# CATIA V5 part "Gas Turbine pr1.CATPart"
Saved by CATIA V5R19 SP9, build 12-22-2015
Part number: PART1
Bounding box of the stored display mesh (mm): x -218.31 to 175.724, y -49.491 to 39.777, z -50 to 67.852
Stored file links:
  C:\Users\hdellam\Desktop\Main Folder\Practice\Turbine\PROTOTYPE.CATPart
  C:\ds\catiaV5R19\sp0a\win_b64\startup\materials\Catalog.CATMaterial
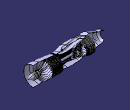
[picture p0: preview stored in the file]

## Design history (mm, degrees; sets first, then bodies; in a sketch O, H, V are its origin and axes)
AxisSystem1: origin (0, 0, 0), X (1, 0, 0), Y (0, 1, 0), Z (0, 0, 1)
Set1
  Plane1: type Offset, RefPlane zx-plane, Offset 29
  Plane2: type Offset, RefPlane Plane1, Offset 10
  Plane3: type Offset, RefPlane yz-plane, Offset -114
  Point1: (-114, 0, 0), in AxisSystem1
  Plane4: type OffsetPt, RefPlane zx-plane, RefPoint Point1
  Plane5: type Offset, RefPlane Plane4, Offset 9
  Plane6: type OffsetPt, RefPlane xy-plane, RefPoint Point1
  Plane7: type Offset, RefPlane Plane6, Offset 37
  Plane8: type Offset, RefPlane Plane5, Offset 27
  Plane9: type Offset, RefPlane zx-plane, Offset 8
  Plane10: type Offset, RefPlane Plane9, Offset 30
  Plane11: type Offset, RefPlane xy-plane, Offset 42
  Plane12: type Offset, RefPlane zx-plane, Offset 10
  Plane13: type Offset, RefPlane Plane4, Offset 19
Body1 (main body)
  Sketch1 on zx-plane, origin (0, 0, 0), H (-1, 0, 0), V (0, 0, 1)
    line L1 (-150, 50) -> (-120, 50)
    line L2 (-120, 50) -> (-30, 40)
    line L3 (-30, 40) -> (-10, 40)
    line L4 (-10, 40) -> (30, 50)
    point P5 (30, 50)
    line L5 (30, 50) -> (90, 50)
    line L6 (90, 50) -> (110, 40)
    point P7 (110, 40)
    line L7 (110, 40) -> (140, 50)
    point P8 (140, 50)
    line L8 (140, 50) -> (190, 30)
    line L9 (190, 30) -> (210, 30)
    line L10 (210, 30) -> (220, 20)
    line L11 (220, 20) -> (220, 0)
    line L12 (-150, 50) -> (-150, 0)
    horizontal: L1 H, L3 H, L5 H, L9 H
    coincidence: P5 L1, P7 L3, P8 L1
    vertical: L11 V, L12 V
  Shaft1: profile Sketch1, axis Sketch1.H, angle -180
  Shell1: IntOffset 1, Face face of Shaft1, ExtOffset 0
  Thickness1: Thickness -1, Face face of Shaft1 from Sketch1.L12
  Sketch2 on zx-plane, origin (0, 0, 0), H (-1, 0, 0), V (0, 0, 1)
    line L1 (218.3102, 24.4495) -> (218.3102, -38.2901)
    line L2 (218.3102, -38.2901) -> (240.7921, -25.6477)
    line L3 (240.7921, -25.6477) -> (239.1356, 27.4033)
    line L4 (239.1356, 27.4033) -> (218.3102, 24.4495)
    vertical: L1 V
  Pocket1: profile Sketch2, direction (0, -1, 0), length 100
  Sketch3 on zx-plane, origin (0, 0, 0), H (-1, 0, 0), V (0, 0, 1)
    line L1 (-30, 30) -> (-80, 30)
    line L2 (-80, 30) -> (-130, 10)
    line L3 (-130, 10) -> (-130, 0)
    line L4 (-30, 30) -> (-30, 0)
    horizontal: L1 H
    vertical: L3 V, L4 V
  Shaft2: profile Sketch3, axis Sketch3.H, angle 360
  Sketch4 on zx-plane, origin (0, 0, 0), H (-1, 0, 0), V (0, 0, 1)
    line L1 (-127.8768, 8.0204) -> (-137.0359, 8.0204)
    line L2 (-137.0359, 8.0204) -> (-137.0359, 0)
    line L3 (-127.8768, 0) -> (-127.8768, 8.0204)
    axis line L4 (-153.3785, 0) -> (-103.6323, 0)
    point P3 (-153.3785, 0)
    point P5 (-137.0359, 0)
    point P6 (-127.8768, 0)
    horizontal: L1 H, L4 H
    vertical: L2 V, L3 V
    coincidence: P3 H, L4 P5, L4 P6
  Shaft3: profile Sketch4, axis Sketch4.L4, angle 360
  Sketch5 on zx-plane, origin (0, 0, 0), H (-1, 0, 0), V (0, 0, 1)
    point P1 (-136.138, 0)
    line L1 (-136.138, 0) -> (-136.138, 9.2757)
    line L2 (-136.138, 9.2757) -> (-139.191, 9.2757)
    line L3 (-139.191, 9.2757) -> (-139.191, 0)
    point P4 (-139.191, 0)
    coincidence: P1 H, P4 H
    vertical: L1 V, L3 V
    horizontal: L2 H
  Shaft4: profile Sketch5, axis Sketch5.H, angle 360
  Sketch6 on zx-plane, origin (0, 0, 0), H (-1, 0, 0), V (0, 0, 1)
    line L1 (-138.293, 7.4825) -> (-138.293, 15.3729)
    line L2 (-138.293, 15.3729) -> (-151.5826, 15.3729)
    line L3 (-151.5826, 15.3729) -> (-174.6721, 1.8721)
    arc A1 centre (-173.5995, 0.0376) radius 2.1251 from (-174.6721, 1.8721) to (-175.7242, 0) ccw
    point P6 (-175.7242, 0)
    vertical: L1 V
    horizontal: L2 H
    coincidence: P6 H
    tangency: A1 L3
  Shaft5: profile Sketch6, axis Sketch6.H, angle 360
  Fillet1: radius 5, on edge [face of Shaft2 from Sketch3.L2 | face of Shaft2 from Sketch3.L1]
  Loft1: solid, Sections (Sketch12; Sketch11)
  CircPattern1: of Loft1, instances 72, angular step 5, axis from edge [XY plane of AxisSystem1 | ZX plane of AxisSystem1]
  RectPattern1: of Loft1, direction 1 instances 4, spacing 12, along edge [XY plane of AxisSystem1 | ZX plane of AxisSystem1]
  CircPattern2: of RectPattern1, instances 72, angular step 5, axis from edge [XY plane of AxisSystem1 | ZX plane of AxisSystem1]
  Sketch7 on zx-plane, origin (0, 0, 0), H (-1, 0, 0), V (0, 0, 1)
    line L1 (-30.3272, 1.5715) -> (166.7698, 1.5715)
    line L2 (166.7698, 1.5715) -> (166.7698, 0)
    point P3 (166.7698, 0)
    horizontal: L1 H
    coincidence: P3 H
    vertical: L2 V
  Shaft6: profile Sketch7, axis edge [XY plane of AxisSystem1 | ZX plane of AxisSystem1], angle 360
  Sketch8 on zx-plane, origin (0, 0, 0), H (-1, 0, 0), V (0, 0, 1)
    point P1 (166.6043, 0)
    line L1 (166.6043, 0) -> (166.6043, 10.2399)
    line L2 (166.6043, 10.2399) -> (183.4256, 0.8538)
    arc A1 centre (182.8409, -0.1941) radius 1.2 from (183.4256, 0.8538) to (184.0251, 0) cw
    point P5 (184.0251, 0)
    radius A1 = 1.2
    coincidence: P1 H, P5 H
    vertical: L1 V
    tangency: A1 L2
  Shaft7: profile Sketch8, axis edge [XY plane of AxisSystem1 | ZX plane of AxisSystem1], angle 360
  Sketch9 on zx-plane, origin (0, 0, 0), H (-1, 0, 0), V (0, 0, 1)
    point P1 (111.9435, 0)
    line L1 (111.9435, 0) -> (111.9435, 21.9862)
    line L2 (111.9435, 21.9862) -> (113.0474, 21.9862)
    line L3 (113.0474, 21.9862) -> (113.0474, 17.7975)
    line L4 (113.0474, 17.7975) -> (113.0474, 9.7257)
    line L5 (113.0474, 9.7257) -> (146.4496, 9.7257)
    line L6 (146.4496, 9.7257) -> (146.4496, 0)
    point P7 (146.4496, 0)
    coincidence: P1 H, P7 H
    vertical: L1 V, L3 V, L4 V, L6 V
    horizontal: L2 H, L5 H
  Shaft8: profile Sketch9, axis axis of face of Shaft6 from Sketch7.L1, angle 360
  Fillet2: radius 10, on edge [face of Shaft5 from Sketch6.L3 | face of Shaft5 from Sketch6.L2]
  Sketch10 on Plane5, origin (0, 9, 0), H (-1, 0, 0), V (0, 0, 1)
    line L1 (119.3854, -1.7606) -> (113.692, 2.1189)
    line L2 (113.692, 2.1189) -> (113.465, 1.7859)
    line L3 (113.465, 1.7859) -> (119.1584, -2.0937)
    line L4 (119.1584, -2.0937) -> (119.3854, -1.7606)
    perpendicularity: L2 L1
    parallelism: L3 L1, L4 L2
  Sketch11 on Plane2, origin (0, 39, 0), H (-1, 0, 0), V (0, 0, 1)
    arc A1 centre (-233.0148, -215.2939) radius 293.2905 from (-31.2101, -2.4697) to (-39.0996, 4.7429) ccw
    arc A2 centre (-4446.4823, -4752.8181) radius 6485.1431 from (-39.259, 4.6458) to (-31.4249, -2.6236) cw
    line L1 (-31.4249, -2.6236) -> (-31.2101, -2.4697)
    line L2 (-39.259, 4.6458) -> (-39.0996, 4.7429)
  Sketch12 on Plane1, origin (0, 29, 0), H (-1, 0, 0), V (0, 0, 1)
    line L1 (-30.9997, -2.4617) -> (-40.1615, 4.4428)
    line L2 (-40.1615, 4.4428) -> (-40.5706, 3.9)
    line L3 (-40.5706, 3.9) -> (-31.4088, -3.0045)
    line L4 (-31.4088, -3.0045) -> (-30.9997, -2.4617)
    perpendicularity: L2 L1
    parallelism: L3 L1, L4 L2
  Sketch13 on Plane8, origin (0, 36, 0), H (-1, 0, 0), V (0, 0, 1)
    line L1 (119.2356, -1.7219) -> (117.5085, 4.4108)
    line L2 (117.5085, 4.4108) -> (117.2852, 4.3479)
    line L3 (117.2852, 4.3479) -> (119.0124, -1.7848)
    line L4 (119.0124, -1.7848) -> (119.2356, -1.7219)
    reference projected line E1 (119.3854, -1.7606) -> (113.692, 2.1189) from Sketch10.L1
    angle L3 E1 = 140
    perpendicularity: L2 L1
    parallelism: L4 L2
  Loft2: solid, Sections (Sketch10; Sketch13)
  CircPattern3: of Loft2, instances 36, angular step 10, axis from edge [XY plane of AxisSystem1 | ZX plane of AxisSystem1]
  RectPattern2: of CircPattern3, direction 1 instances 3, spacing 10, along edge [XY plane of AxisSystem1 | ZX plane of AxisSystem1] reversed
  Loft3: solid, Sections (Sketch34; Sketch33)
  CircPattern4: of Loft3, instances 24, angular step 15, axis from edge [XY plane of AxisSystem1 | ZX plane of AxisSystem1]
  Sketch14 on Plane8, origin (0, 36, 0), H (-1, 0, 0), V (0, 0, 1)
    line L1 (146.4895, 11.6459) -> (186.6123, 11.6459)
    line L2 (186.6123, 11.6459) -> (186.6123, -11.4296)
    line L3 (186.6123, -11.4296) -> (146.4895, -11.4296)
    line L4 (146.4895, -11.4296) -> (146.4895, 11.6459)
    horizontal: L1 H, L3 H
    vertical: L2 V, L4 V
  Pocket2: profile Sketch14, direction (0, -1, 0), length 61
  Sketch15 on Plane4, origin (0, 0, 0), H (-1, 0, 0), V (0, 0, 1)
    point P1 (146.3286, 0)
    line L1 (146.3286, 0) -> (146.3286, 19.8868)
    line L2 (146.3286, 19.8868) -> (176.7975, 2.5259)
    arc A1 centre (175.3905, 0.0565) radius 2.8421 from (176.7975, 2.5259) to (178.232, 0) cw
    point P5 (178.232, 0)
    coincidence: P1 H, P5 H
    vertical: L1 V
    tangency: A1 L2
  Shaft9: profile Sketch15, axis edge [XY plane of AxisSystem1 | ZX plane of AxisSystem1], angle 360
  Sketch16 on zx-plane, origin (0, 0, 0), H (-1, 0, 0), V (0, 0, 1)
    spline S1 through (-30.074, 15.6457) (18.9189, 15.6457) (34.6576, 18.6875) (42.1461, 21.9827) (50.5232, 24.0105) (61.3118, 20.842) (70.0696, 22.6164) (89.3621, 30.3475) (111.8278, 32.6288)
    line L1 (111.8278, 32.6288) -> (112.0612, 32.6288)
    line L2 (112.0612, 32.6288) -> (112.0612, 0)
    point P2 (112.0612, 0)
    point P3 (111.8278, 32.6288)
    line L3 (-30.074, 15.6457) -> (-30.074, 0)
    point P4 (-30.074, 0)
    point P5 (-30.074, 15.6457)
    point P6 (111.8278, 32.6288)
    point P7 (-30.074, 15.6457)
    horizontal: L1 H
    coincidence: P2 H, P6 P3, P4 H, P7 P5
    vertical: L2 V, L3 V
  Shaft10: profile Sketch16, axis edge [XY plane of AxisSystem1 | ZX plane of AxisSystem1], angle 180
  Sketch17 on face of Shaft10, origin (0, 0, 0), H (-1, 0, 0), V (0, 0, 1)
    frozenspline C1
    line L1 (-29.4998, 14.792) -> (-29.4998, 1.5715)
    line L2 (-29.4998, 1.5715) -> (111.2751, 1.5715)
    line L3 (111.2751, 1.5715) -> (111.2751, 31.741)
    vertical: L1 V, L3 V
    horizontal: L2 H
  Groove1: profile Sketch17, axis edge [XY plane of AxisSystem1 | ZX plane of AxisSystem1], angle 180
  Thickness2: Thickness -2, Face face of Shaft10 from Sketch16.L2
  Thickness3: Thickness -2, Face face of Groove1 from Sketch17.L1
  Thickness4: Thickness 1.5, Face face of Groove1 from Sketch17.L1
  Sketch18 on zx-plane, origin (0, 0, 0), H (-1, 0, 0), V (0, 0, 1)
    spline S1 through (112.1552, 7.4542) (92.5629, 7.4542) (90.1656, 7.8669)
    line L1 (90.1656, 7.8669) -> (90.1656, 7.4542)
    line L2 (90.1656, 7.4542) -> (89.5042, 7.4542)
    line L3 (89.5042, 7.4542) -> (89.5042, 7.8669)
    line L4 (89.5042, 7.8669) -> (88.7602, 7.8669)
    line L5 (88.7602, 7.8669) -> (88.7602, 7.4542)
    point P5 (88.7602, 7.4542)
    line L6 (88.7602, 7.4542) -> (88.1815, 7.4542)
    line L7 (88.1815, 7.4542) -> (88.1815, 7.8669)
    point P7 (88.1815, 7.8669)
    line L8 (88.1815, 7.8669) -> (53.461, 7.8669)
    line L9 (53.461, 7.8669) -> (51.725, 5.5556)
    line L10 (51.725, 5.5556) -> (-19.5672, 5.5556)
    line L11 (-19.5672, 5.5556) -> (-24.8579, 0)
    point P11 (-24.8579, 0)
    point P12 (90.1656, 7.8669)
    line L12 (112.1552, 7.4542) -> (112.1552, 0)
    point P13 (112.1552, 0)
    point P14 (112.1552, 7.4542)
    point P15 (90.1656, 7.8669)
    point P16 (112.1552, 7.4542)
    vertical: L1 V, L3 V, L5 V, L7 V, L12 V
    horizontal: L2 H, L4 H, L6 H, L8 H, L10 H
    coincidence: P5 L2, P7 L4, P11 H, P15 P12, P13 H, P16 P14
  Shaft11: profile Sketch18, axis edge [XY plane of AxisSystem1 | ZX plane of AxisSystem1], angle 360
  Sketch19 on zx-plane, origin (0, 0, 0), H (-1, 0, 0), V (0, 0, 1)
    line L1 (-13.0972, 4.2651) -> (-15.5794, 7.0019)
    line L2 (-15.5794, 7.0019) -> (-18.7339, 7.0019)
    point P3 (-18.7339, 7.0019)
    spline S1 through (-18.7339, 7.0019) (-30.3693, 8.8608) (-31.2484, 9.7387)
    line L3 (-31.2484, 9.7387) -> (-31.2484, 0)
    point P4 (-31.2484, 0)
    point P5 (-31.2484, 9.7387)
    line L4 (-13.0972, 4.2651) -> (-13.0972, 0)
    point P6 (-13.0972, 0)
    point P7 (-18.7339, 7.0019)
    point P8 (-31.2484, 9.7387)
    horizontal: L2 H
    coincidence: P7 P3, P4 H, P8 P5, P6 H
    vertical: L3 V, L4 V
  Shaft12: profile Sketch19, axis edge [XY plane of AxisSystem1 | ZX plane of AxisSystem1], angle 360
  Sketch20 on zx-plane, origin (0, 0, 0), H (-1, 0, 0), V (0, 0, 1)
    point P1 (-13.8364, 15.1906)
    line L1 (-13.8364, 15.1906) -> (-13.8364, 0)
    point P2 (-13.8364, 0)
    line L2 (-13.8364, 0) -> (-12.3364, 0)
    point P3 (-12.3364, 0)
    line L3 (-12.3364, 0) -> (-12.3364, 15.1906)
    point P4 (-12.3364, 15.1906)
    line L4 (-12.3364, 15.1906) -> (-9.3364, 15.1906)
    point P5 (-9.3364, 15.1906)
    line L5 (-9.3364, 15.1906) -> (-9.3364, 0)
    point P6 (-9.3364, 0)
    line L6 (-9.3364, 0) -> (-8.5864, 0)
    point P7 (-8.5864, 0)
    construction line L7 (-8.5864, -11.0919) -> (-8.5864, 53.0563)
    point P10 (-3.3364, 15.1906)
    point P11 (-3.3364, 0)
    point P12 (-4.8364, 0)
    point P13 (-4.8364, 15.1906)
    point P14 (-7.8364, 15.1906)
    point P15 (-7.8364, 0)
    point P16 (-8.5864, 0)
    line L8 (-3.3364, 15.1906) -> (-3.3364, 0)
    line L9 (-3.3364, 0) -> (-4.8364, 0)
    line L10 (-4.8364, 0) -> (-4.8364, 15.1906)
    line L11 (-4.8364, 15.1906) -> (-7.8364, 15.1906)
    line L12 (-7.8364, 15.1906) -> (-7.8364, 0)
    line L13 (-7.8364, 0) -> (-8.5864, 0)
    construction line L14 (-1.8483, -3.8589) -> (-1.8483, 48.8697)
    point P19 (10.1398, 15.1906)
    point P20 (10.1398, 0)
    point P21 (8.6398, 0)
    point P22 (8.6398, 15.1906)
    point P23 (5.6398, 15.1906)
    point P24 (5.6398, 0)
    point P25 (4.8898, 0)
    point P26 (-0.3602, 15.1906)
    point P27 (-0.3602, 0)
    point P28 (1.1398, 0)
    point P29 (1.1398, 15.1906)
    point P30 (4.1398, 15.1906)
    point P31 (4.1398, 0)
    point P32 (4.8898, 0)
    line L15 (10.1398, 15.1906) -> (10.1398, 0)
    line L16 (10.1398, 0) -> (8.6398, 0)
    line L17 (8.6398, 0) -> (8.6398, 15.1906)
    line L18 (8.6398, 15.1906) -> (5.6398, 15.1906)
    line L19 (5.6398, 15.1906) -> (5.6398, 0)
    line L20 (5.6398, 0) -> (4.8898, 0)
    line L21 (-0.3602, 15.1906) -> (-0.3602, 0)
    line L22 (-0.3602, 0) -> (1.1398, 0)
    line L23 (1.1398, 0) -> (1.1398, 15.1906)
    line L24 (1.1398, 15.1906) -> (4.1398, 15.1906)
    line L25 (4.1398, 15.1906) -> (4.1398, 0)
    line L26 (4.1398, 0) -> (4.8898, 0)
    construction line L27 (10.7077, -10.0588) -> (10.7077, 50.5891)
    point P35 (21.4155, 0)
    construction line L28 through (21.4155, 0) direction (0, 1)
    point P36 (35.2519, 15.1906)
    point P37 (35.2519, 0)
    point P38 (33.7519, 0)
    point P39 (33.7519, 15.1906)
    point P40 (30.7519, 15.1906)
    point P41 (30.7519, 0)
    point P42 (30.0019, 0)
    point P43 (24.7519, 15.1906)
    point P44 (24.7519, 0)
    point P45 (26.2519, 0)
    point P46 (26.2519, 15.1906)
    point P47 (29.2519, 15.1906)
    point P48 (29.2519, 0)
    point P49 (30.0019, 0)
    point P50 (11.2757, 15.1906)
    point P51 (11.2757, 0)
    point P52 (12.7757, 0)
    point P53 (12.7757, 15.1906)
    point P54 (15.7757, 15.1906)
    point P55 (15.7757, 0)
    point P56 (16.5257, 0)
    point P57 (21.7757, 15.1906)
    point P58 (21.7757, 0)
    point P59 (20.2757, 0)
    point P60 (20.2757, 15.1906)
    point P61 (17.2757, 15.1906)
    point P62 (17.2757, 0)
    point P63 (16.5257, 0)
    line L29 (35.2519, 15.1906) -> (35.2519, 0)
    line L30 (35.2519, 0) -> (33.7519, 0)
    line L31 (33.7519, 0) -> (33.7519, 15.1906)
    line L32 (30.7519, 15.1906) -> (30.7519, 0)
    line L33 (30.7519, 0) -> (30.0019, 0)
    line L34 (24.7519, 15.1906) -> (24.7519, 0)
    line L35 (24.7519, 0) -> (26.2519, 0)
    line L36 (26.2519, 0) -> (26.2519, 15.1906)
    line L37 (29.2519, 15.1906) -> (29.2519, 0)
    line L38 (29.2519, 0) -> (30.0019, 0)
    line L39 (11.2757, 15.1906) -> (11.2757, 0)
    line L40 (11.2757, 0) -> (12.7757, 0)
    line L41 (12.7757, 0) -> (12.7757, 15.1906)
    line L42 (12.7757, 15.1906) -> (15.7757, 15.1906)
    line L43 (15.7757, 15.1906) -> (15.7757, 0)
    line L44 (15.7757, 0) -> (16.5257, 0)
    line L45 (21.7757, 15.1906) -> (21.7757, 0)
    line L46 (21.7757, 0) -> (20.2757, 0)
    line L47 (20.2757, 0) -> (20.2757, 15.1906)
    line L48 (20.2757, 15.1906) -> (17.2757, 15.1906)
    line L49 (17.2757, 15.1906) -> (17.2757, 0)
    line L50 (17.2757, 0) -> (16.5257, 0)
    point P70 (43.5019, 0)
    point P77 (43.5019, 0)
    point P78 (36.7519, 30.5992)
    line L51 (38.2519, 15.1906) -> (38.2519, 0)
    line L52 (38.2519, 0) -> (39.7519, 0)
    line L53 (39.7519, 0) -> (39.7519, 15.1906)
    line L54 (42.7519, 15.1906) -> (42.7519, 0)
    line L55 (42.7519, 0) -> (43.5019, 0)
    line L56 (48.7519, 17) -> (48.7519, 0)
    line L57 (48.7519, 0) -> (47.2519, 0)
    line L58 (47.2519, 0) -> (47.2519, 15.1906)
    line L59 (44.2519, 15.1906) -> (44.2519, 0)
    line L60 (44.2519, 0) -> (43.5019, 0)
    line L61 (21.7757, 15.1906) -> (21.7757, 15.613)
    line L62 (21.7757, 15.613) -> (24.7519, 16.0955)
    point P80 (24.7519, 16.0955)
    line L63 (24.7519, 16.0955) -> (24.7519, 15.1906)
    line L64 (26.2519, 15.1906) -> (26.2519, 16.3386)
    point P81 (26.2519, 16.3386)
    line L65 (26.2519, 16.3386) -> (29.2519, 16.7223)
    point P82 (29.2519, 16.7223)
    line L66 (29.2519, 16.7223) -> (29.2519, 15.1906)
    line L67 (30.7519, 15.1906) -> (30.7519, 16.9142)
    point P83 (30.7519, 16.9142)
    line L68 (30.7519, 16.9142) -> (33.7519, 18.0632)
    point P84 (33.7519, 18.0632)
    line L69 (33.7519, 18.0632) -> (33.7519, 15.1906)
    line L70 (35.2519, 15.1906) -> (35.2519, 18.6377)
    point P85 (35.2519, 18.6377)
    line L71 (35.2519, 18.6377) -> (38.2519, 20.0154)
    point P86 (38.2519, 20.0154)
    line L72 (38.2519, 20.0154) -> (38.2519, 15.1906)
    line L73 (39.7519, 15.1906) -> (39.7519, 20.7042)
    point P87 (39.7519, 20.7042)
    line L74 (39.7519, 20.7042) -> (42.7519, 21.8532)
    point P88 (42.7519, 21.8532)
    line L75 (42.7519, 21.8532) -> (42.7519, 15.1906)
    line L76 (44.2519, 15.1906) -> (44.2519, 22.4277)
    point P89 (44.2519, 22.4277)
    line L77 (44.2519, 22.4277) -> (47.2519, 23.2338)
    point P90 (47.2519, 23.2338)
    line L78 (47.2519, 23.2338) -> (47.2519, 15.1906)
    line L79 (48.7519, 17) -> (48.7519, 23.091)
    line L80 (-13.8364, 15.1906) -> (-13.5858, 15.425)
    line L81 (-13.5858, 15.425) -> (-10.5695, 15.425)
    line L82 (-10.5695, 15.425) -> (-6.1807, 15.3851)
    line L83 (-6.1807, 15.3851) -> (1.422, 15.3851)
    line L84 (1.422, 15.3851) -> (5.0049, 15.3851)
    line L85 (5.0049, 15.3851) -> (11.6178, 15.425)
    line L86 (11.6178, 15.425) -> (13.9798, 15.425)
    line L87 (13.9798, 15.425) -> (19.7054, 15.5126)
    line L88 (19.7054, 15.5126) -> (21.6918, 15.8346)
    line L89 (21.6918, 15.8346) -> (25.1026, 16.2708)
    line L90 (25.1026, 16.2708) -> (29.5145, 16.9142)
    line L91 (29.5145, 16.9142) -> (33.7868, 18.3014)
    line L92 (33.7868, 18.3014) -> (35.8655, 19.0976)
    line L93 (35.8655, 19.0976) -> (39.2043, 20.5484)
    line L94 (39.2043, 20.5484) -> (42.5973, 22.0228)
    line L95 (42.5973, 22.0228) -> (44.6745, 22.7397)
    line L96 (44.6745, 22.7397) -> (47.5459, 23.5112)
    line L97 (47.5459, 23.5112) -> (48.6881, 23.5112)
    line L98 (48.6881, 23.5112) -> (48.7519, 23.091)
    line L99 (-0.3602, 15.1906) -> (-3.3364, 15.1906)
    line L100 (10.1398, 15.1906) -> (11.2757, 15.1906)
    length L4 = 3
    length L2 = 1.5
    length L6 = 0.75
    length L56 = 17
    coincidence: P2 H, P6 H, P80 L34, P81 L62, P82 L37, L65 P61, P83 L65, P84 L31, L68 P46, P85 L68, P86 L51, P87 L71, P88 L54, P89 L74, P90 L68, P90 L58, P7 P16, P25 P32, P42 P49, P56 P63, P70 P77
    vertical: L1 V, L3 V, L5 V, L7 V, L14 V, L27 V, L61 V, L63 V, L64 V, L66 V, L67 V, L69 V, L70 V, L72 V, L73 V, L75 V, L76 V, L78 V, L79 V
    horizontal: L2 H, L4 H, L6 H, L81 H, L83 H, L84 H, L86 H, L97 H, L99 H, L100 H
    symmetry: P1 P10 L7, P2 P11 L7, P3 P12 L7, P4 P13 L7, P5 P14 L7, P6 P15 L7, P7 P16 L7, L1 L8 L7, L2 L9 L7, L3 L10 L7, L4 L11 L7, L5 L12 L7, L6 L13 L7, P1 P19 L14, P2 P20 L14, P3 P21 L14, P4 P22 L14, P5 P23 L14, P6 P24 L14, P7 P25 L14, P10 P26 L14, P11 P27 L14, P12 P28 L14, P13 P29 L14, P14 P30 L14, P15 P31 L14, P16 P32 L14, L1 L15 L14, L2 L16 L14, L3 L17 L14, L4 L18 L14, L5 L19 L14, L6 L20 L14, L8 L21 L14, L9 L22 L14, L10 L23 L14, L11 L24 L14, L12 L25 L14, L13 L26 L14, O P35 L27, V L28 L27, P1 P36 L27, P2 P37 L27, P3 P38 L27, P4 P39 L27, P5 P40 L27, P6 P41 L27, P7 P42 L27, P10 P43 L27, P11 P44 L27, P12 P45 L27, P13 P46 L27, P14 P47 L27, P15 P48 L27, P16 P49 L27, P19 P50 L27, P20 P51 L27, P21 P52 L27, P22 P53 L27, P23 P54 L27, P24 P55 L27, P25 P56 L27, P26 P57 L27, P27 P58 L27, P28 P59 L27, P29 P60 L27, P30 P61 L27, P31 P62 L27, P32 P63 L27, L2 L30 L27, L6 L33 L27, L9 L35 L27, L13 L38 L27, L15 L39 L27, L16 L40 L27, L17 L41 L27, L18 L42 L27, L19 L43 L27, L20 L44 L27, L22 L46 L27, L23 L47 L27, L24 L48 L27, L25 L49 L27, L26 L50 L27
    parallelism: L74 L68, L88 L62, L89 L65, L92 L74, L94 L93, L96 L77
  Shaft13: profile Sketch20, axis edge [XY plane of AxisSystem1 | ZX plane of AxisSystem1], angle 180
  Sketch21 on zx-plane, origin (0, 0, 0), H (-1, 0, 0), V (0, 0, 1)
    line L1 (-14.0123, 5.5556) -> (-14.0123, 6.1326)
    line L2 (-14.0123, 6.1326) -> (49.2396, 6.1326)
    line L3 (49.2396, 6.1326) -> (49.2396, 5.5556)
    line L4 (49.2396, 5.5556) -> (48.8265, 5.5556)
    line L5 (48.8265, 5.5556) -> (-14.0123, 5.5556)
    vertical: L1 V, L3 V
    horizontal: L2 H, L4 H, L5 H
  Groove2: profile Sketch21, axis edge [XY plane of AxisSystem1 | ZX plane of AxisSystem1], angle 180
  Sketch22 on Plane11, origin (0, 0, 42), H (1, 0, 0), V (0, 1, 0)
    circle A1 centre (0, 0) radius 2.5
    radius A1 = 2.5
  Sketch23 on zx-plane, origin (0, 0, 0), H (-1, 0, 0), V (0, 0, 1)
    spline S1 through (-0.3851, 42.3929) (1.2237, 54.7141) (16.8917, 57.1722) (46.1157, 59.8514) (120.8629, 48.6722)
    arc A1 centre (104.8693, 27.0835) radius 26.8675 from (120.8629, 48.6722) to (125.2658, 44.572) cw
    point P1 (120.8629, 48.6722)
    point P5 (120.8629, 48.6722)
    coincidence: P5 P1
  Rib1: profile Sketch22, centre curve Sketch23
  Sketch24 on Plane11, origin (0, 0, 42), H (1, 0, 0), V (0, 1, 0)
    circle A1 centre (0, 0) radius 3.5075
  Sketch25 on zx-plane, origin (0, 0, 0), H (-1, 0, 0), V (0, 0, 1)
    spline S1 through (-0.3851, 42.3929) (-0.793, 46.5052)
  Rib2: profile Sketch24, centre curve Sketch25
  Sketch26 on Plane12, origin (0, 10, 0), H (-1, 0, 0), V (0, 0, 1)
    line L1 (7.5245, 44.3811) -> (-6, 41)
    line L2 (-6, 41) -> (-5.1628, 39.3306)
    line L3 (-5.1628, 39.3306) -> (9.0614, 43.0762)
    line L4 (9.0614, 43.0762) -> (7.5245, 44.3811)
  Pocket3: profile Sketch26, direction (0, -1, 0), length 10
  Sketch27 on face of Pocket3, origin (0, 0, 0), H (-1, 0, 0), V (0, 0, 1)
    point P1 (1.039, 41.729)
    line L1 (1.039, 41.729) -> (6.6385, 43.1288)
    line L2 (6.6385, 43.1288) -> (6.4235, 42.8545)
    line L3 (6.4235, 42.8545) -> (3.668, 42.1656)
    line L4 (3.668, 42.1656) -> (3.6149, 41.9234)
    line L5 (3.6149, 41.9234) -> (2.8356, 41.8646)
    line L6 (2.8356, 41.8646) -> (1.5366, 41.729)
    line L7 (1.5366, 41.729) -> (1.039, 41.729)
    parallelism: L3 L1
    coincidence: L5 P1
    horizontal: L7 H
  Groove3: profile Sketch27, axis edge [XY plane of AxisSystem1 | ZX plane of AxisSystem1], angle 180
  Sketch28 on zx-plane, origin (0, 0, 0), H (-1, 0, 0), V (0, 0, 1)
    line L1 (-14.9881, 15.4952) -> (-14.9881, 31.7771)
    point P2 (-14.9881, 31.7771)
    spline S1 through (-14.9881, 31.7771) (101.169, 36.6449) (106.8844, 36.6449) (113.9446, 35.8056)
    spline S2 through (-14.2382, 30.9214) (101.9189, 35.7892) (107.6343, 35.7892) (114.6945, 34.9499)
    line L2 (-14.2382, 30.9214) -> (-14.2382, 15.4952)
    line L3 (-14.2382, 15.4952) -> (-14.9881, 15.4952)
    point P4 (-14.2382, 30.9214)
    line L4 (114.6945, 34.9499) -> (113.9446, 35.8056)
    point P5 (113.9446, 35.8056)
    point P6 (114.6945, 34.9499)
    point P7 (-14.9881, 31.7771)
    point P8 (-14.2382, 30.9214)
    point P9 (113.9446, 35.8056)
    point P10 (114.6945, 34.9499)
    vertical: L1 V, L2 V
    coincidence: P7 P2, P8 P4, P9 P5, P10 P6
    horizontal: L3 H
  Shaft14: profile Sketch28, axis edge [XY plane of AxisSystem1 | ZX plane of AxisSystem1], angle 180
  Thickness5: Thickness -0.75, Face face of Shaft14 from Sketch28.L1
  Sketch29 on zx-plane, origin (0, 0, 0), H (-1, 0, 0), V (0, 0, 1)
    spline S1 through (-13.2871, 29.4946) (10.0827, 22.3031) (17.6522, 21.4959) (32.6441, 22.3031) (34.7753, 22.7434)
    spline S2 through (-13.2871, 28.9075) (10.0827, 21.716) (17.6522, 20.9088) (32.6441, 21.716) (34.7753, 22.1563)
    line L1 (-13.2871, 29.4946) -> (-13.2871, 28.9075)
    point P1 (-13.2871, 28.9075)
    point P2 (-13.2871, 29.4946)
    line L2 (34.7753, 22.7434) -> (34.7753, 22.1563)
    point P3 (34.7753, 22.1563)
    point P4 (34.7753, 22.7434)
    point P5 (34.7753, 20.9872)
    point P6 (34.7753, 21.5742)
    line L3 (34.7753, 21.5742) -> (34.7753, 20.9872)
    spline S3 through (-13.2871, 28.3254) (10.0827, 21.1339) (17.6522, 20.3267) (32.6441, 21.1339) (34.7753, 21.5742)
    spline S4 through (-13.2871, 27.7384) (10.0827, 20.5469) (17.6522, 19.7397) (32.6441, 20.5469) (34.7753, 20.9872)
    point P7 (-13.2871, 27.7384)
    point P8 (-13.2871, 28.3254)
    line L4 (-13.2871, 28.3254) -> (-13.2871, 27.7384)
    spline S5 through (-13.2871, 26.9391) (10.0827, 19.7476) (17.6522, 18.9404) (32.6441, 19.7476) (34.7753, 20.1879)
    spline S6 through (-13.2871, 26.3521) (10.0827, 19.1606) (17.6522, 18.3534) (32.6441, 19.1606) (34.7753, 19.6009)
    point P9 (34.7753, 19.6009)
    point P10 (34.7753, 20.1879)
    line L5 (34.7753, 20.1879) -> (34.7753, 19.6009)
    point P11 (-13.2871, 26.3521)
    point P12 (-13.2871, 26.9391)
    line L6 (-13.2871, 26.9391) -> (-13.2871, 26.3521)
    point P13 (-13.2871, 28.9075)
    point P14 (-13.2871, 29.4946)
    point P15 (34.7753, 22.1563)
    point P16 (34.7753, 22.7434)
    point P17 (34.7753, 20.9872)
    point P18 (34.7753, 21.5742)
    point P19 (-13.2871, 28.3254)
    point P20 (-13.2871, 27.7384)
    point P21 (-13.2871, 26.9391)
    point P22 (34.7753, 20.1879)
    point P23 (-13.2871, 26.3521)
    point P24 (34.7753, 19.6009)
    coincidence: P13 P1, P14 P2, P15 P3, P16 P4, P5 P17, P6 P18, P19 P8, P20 P7, P21 P12, P22 P10, P23 P11, P24 P9
    vertical: L1 V, L2 V
  Shaft15: profile Sketch29, axis edge [XY plane of AxisSystem1 | ZX plane of AxisSystem1], angle 180
  Sketch30 on zx-plane, origin (0, 0, 0), H (-1, 0, 0), V (0, 0, 1)
    spline S1 through (-11.9865, 24.3326) (8.0647, 18.2993) (18.135, 17.5842)
    spline S2 through (-11.9865, 23.7963) (8.0647, 17.763) (18.135, 17.0479)
    spline S3 through (-11.9865, 22.3662) (6.4534, 17.0479) (7.8409, 16.8244)
    spline S4 through (-11.9865, 21.8299) (6.4534, 16.5116) (7.8409, 16.2881)
    spline S5 through (-11.9865, 20.7486) (-3.4466, 17.763) (1.2745, 16.8244)
    spline S6 through (-11.9865, 20.3023) (-3.4466, 17.3166) (1.2745, 16.3781)
    line L1 (-11.9865, 24.3326) -> (-11.9865, 23.7963)
    point P1 (-11.9865, 23.7963)
    point P2 (-11.9865, 24.3326)
    line L2 (-11.9865, 22.3662) -> (-11.9865, 21.8299)
    point P3 (-11.9865, 21.8299)
    point P4 (-11.9865, 22.3662)
    line L3 (-11.9865, 20.7486) -> (-11.9865, 20.3023)
    point P5 (-11.9865, 20.3023)
    point P6 (-11.9865, 20.7486)
    line L4 (1.2745, 16.8244) -> (1.2745, 16.3781)
    point P7 (1.2745, 16.3781)
    point P8 (1.2745, 16.8244)
    line L5 (7.8409, 16.2881) -> (7.8409, 16.8244)
    point P9 (7.8409, 16.8244)
    point P10 (7.8409, 16.2881)
    line L6 (18.135, 17.5842) -> (18.135, 17.0479)
    point P11 (18.135, 17.0479)
    point P12 (18.135, 17.5842)
    point P13 (-11.9865, 23.7963)
    point P14 (-11.9865, 24.3326)
    point P15 (-11.9865, 21.8299)
    point P16 (-11.9865, 22.3662)
    point P17 (-11.9865, 20.3023)
    point P18 (-11.9865, 20.7486)
    point P19 (1.2745, 16.8244)
    point P20 (1.2745, 16.3781)
    point P21 (7.8409, 16.8244)
    point P22 (7.8409, 16.2881)
    point P23 (18.135, 17.0479)
    point P24 (18.135, 17.5842)
    coincidence: P13 P1, P14 P2, P15 P3, P16 P4, P17 P5, P18 P6, P20 P7, P19 P8, P21 P9, P22 P10, P23 P11, P24 P12
    vertical: L1 V, L2 V, L3 V, L4 V, L5 V, L6 V
  Shaft16: profile Sketch30, axis edge [XY plane of AxisSystem1 | ZX plane of AxisSystem1], angle 180
  Sketch31 on Plane4, origin (0, 0, 0), H (-1, 0, 0), V (0, 0, 1)
    spline S1 through (62.6135, -2.0846) (55.9376, 3.3543) (54.932, 3.6332)
    spline S2 through (62.5716, -2.322) (55.8958, 3.1169) (54.8902, 3.3958)
    line L1 (54.932, 3.6332) -> (54.8902, 3.3958)
    point P1 (54.8902, 3.3958)
    point P2 (54.932, 3.6332)
    line L2 (62.6135, -2.0846) -> (62.5716, -2.322)
    point P3 (62.5716, -2.322)
    point P4 (62.6135, -2.0846)
    point P5 (73.6171, 3.7537)
    point P6 (73.8356, 3.6518)
    point P7 (66.106, -2.1861)
    point P8 (66.3245, -2.288)
    spline S3 through (66.3245, -2.288) (73.3059, 2.7527) (73.8356, 3.6518)
    spline S4 through (66.106, -2.1861) (73.0874, 2.8546) (73.6171, 3.7537)
    line L3 (73.8356, 3.6518) -> (73.6171, 3.7537)
    line L4 (66.3245, -2.288) -> (66.106, -2.1861)
    point P9 (76.8335, 3.3958)
    point P10 (76.8753, 3.6332)
    point P11 (84.5149, -2.322)
    point P12 (84.5568, -2.0846)
    spline S5 through (84.5568, -2.0846) (77.8809, 3.3543) (76.8753, 3.6332)
    spline S6 through (84.5149, -2.322) (77.8391, 3.1169) (76.8335, 3.3958)
    line L5 (76.8753, 3.6332) -> (76.8335, 3.3958)
    line L6 (84.5568, -2.0846) -> (84.5149, -2.322)
    point P13 (54.8902, 3.3958)
    point P14 (54.932, 3.6332)
    point P15 (62.5716, -2.322)
    point P16 (62.6135, -2.0846)
    point P17 (73.6171, 3.7537)
    point P18 (73.8356, 3.6518)
    point P19 (66.106, -2.1861)
    point P20 (66.3245, -2.288)
    point P21 (76.8335, 3.3958)
    point P22 (76.8753, 3.6332)
    point P23 (84.5149, -2.322)
    point P24 (84.5568, -2.0846)
    coincidence: P13 P1, P14 P2, P15 P3, P16 P4, P5 P17, P6 P18, P7 P19, P8 P20, P9 P21, P10 P22, P11 P23, P12 P24
    parallelism: L2 L1
  Pad1: profile Sketch31, direction (0, 1, 0), length 18
  CircPattern5: of Pad1, instances 24, angular step 15, axis from edge [XY plane of AxisSystem1 | ZX plane of AxisSystem1]
  Sketch32 on Plane4, origin (0, 0, 0), H (-1, 0, 0), V (0, 0, 1)
    point P1 (102.6863, 3.6332)
    point P2 (110.3677, -2.0846)
    point P3 (102.6445, 3.3958)
    point P4 (102.6863, 3.6332)
    point P5 (110.3677, -2.0846)
    point P6 (110.3259, -2.322)
    point P7 (110.3259, -2.322)
    point P8 (102.6445, 3.3958)
    point P9 (99.6466, 3.6518)
    point P10 (92.1355, -2.288)
    point P11 (99.4281, 3.7537)
    point P12 (99.6466, 3.6518)
    point P13 (91.917, -2.1861)
    point P14 (99.4281, 3.7537)
    point P15 (92.1355, -2.288)
    point P16 (91.917, -2.1861)
    frozenspline C1
    line L1 (102.6863, 3.6332) -> (102.6445, 3.3958)
    line L2 (110.3259, -2.322) -> (110.3677, -2.0846)
    frozenspline C2
    frozenspline C3
    line L3 (99.6466, 3.6518) -> (99.4281, 3.7537)
    frozenspline C4
    line L4 (91.917, -2.1861) -> (92.1355, -2.288)
    coincidence: P1 P4, P2 P5, P3 P8, P6 P7, P9 P12, P10 P15, P11 P14, P13 P16
  Pad2: profile Sketch32, direction (0, 1, 0), length 28
  CircPattern6: of Pad2, instances 24, angular step 15, axis from edge [XY plane of AxisSystem1 | ZX plane of AxisSystem1]
  Sketch33 on Plane10, origin (0, 38, 0), H (-1, 0, 0), V (0, 0, 1)
    frozenspline C1
    frozenspline C2
    line L1 (-114.105, -0.0037) -> (-114.0289, -0.109)
    line L2 (-87.1339, 11.7669) -> (-87.1948, 11.8678)
  Sketch34 on Plane9, origin (0, 8, 0), H (-1, 0, 0), V (0, 0, 1)
    spline S1 through (-127.933, 1.5711) (-106.475, 3.2542) (-85.6004, 8.3681)
    line L1 (-85.6004, 8.3681) -> (-85.5619, 8.2567)
    point P1 (-85.5619, 8.2567)
    point P2 (-85.6004, 8.3681)
    line L2 (-127.933, 1.5711) -> (-127.933, 1.5334)
    point P3 (-127.933, 1.5334)
    point P4 (-127.933, 1.5711)
    spline S2 through (-127.933, 1.5334) (-106.3778, 3.0102) (-100.9289, 4.0628) (-86.3715, 7.9764) (-85.5619, 8.2567)
    point P5 (-85.6004, 8.3681)
    point P6 (-127.933, 1.5711)
    point P7 (-127.933, 1.5334)
    point P8 (-85.5619, 8.2567)
    coincidence: P5 P2, P6 P4, P7 P3, P8 P1
    vertical: L2 V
